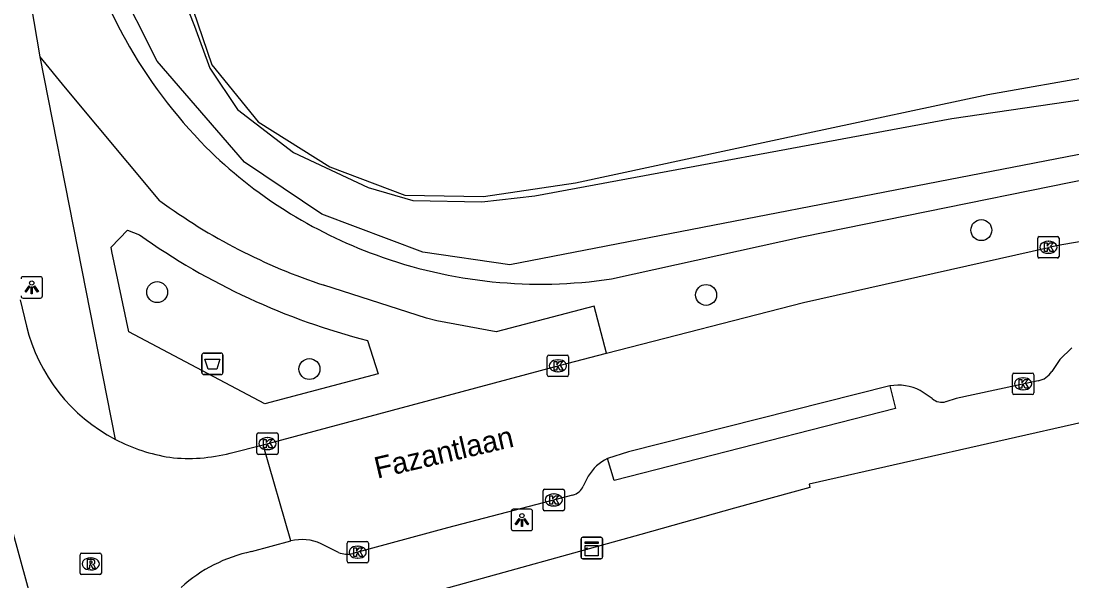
# Model space of a CAD drawing. Extents: x 161772 to 163123, y 383092 to 383917.
# Drawn here: x 161963.46 to 162012.54, y 383457.54 to 383483.68 of the extents above; entities that cross this region are included whole.
import ezdxf

# ---------------------------------------------------------------- set-up
doc = ezdxf.new("R2010")
doc.units = 0
for name, color, linetype in [('IMGEO_Afvalbak', 7, 'Continuous'), ('IMGEO_Boom', 7, 'Continuous'), ('IMGEO_Erf', 7, 'Continuous'), ('IMGEO_Groenvoorziening', 7, 'Continuous'), ('IMGEO_Kast', 7, 'Continuous'), ('IMGEO_Kolk', 7, 'Continuous'), ('IMGEO_Lichtpunt', 7, 'Continuous'), ('IMGEO_Openbare_ruimte_label', 7, 'Continuous'), ('IMGEO_Rijbaan_lokaal_gesloten', 7, 'Continuous'), ('IMGEO_Rijbaan_lokaal_open', 7, 'Continuous'), ('IMGEO_Rioolput', 7, 'Continuous'), ('IMGEO_Voetpad_gesloten', 7, 'Continuous'), ('IMGEO_Voetpad_open', 7, 'Continuous'), ('IMGEO_Waterloop', 7, 'Continuous')]:
    doc.layers.add(name, color=color, linetype=linetype)

msp = doc.modelspace()

# ---------------------------------------------------------------- linework, layer by layer
at = {"layer": 'IMGEO_Afvalbak'}
for p, q in [((161971.902, 383467.276), (161971.902, 383468.076)), ((161971.902, 383468.076), (161971.902, 383467.276)), ((161972.002, 383468.176), (161972.792, 383468.176)), ((161972.792, 383468.176), (161972.002, 383468.176)), ((161972.892, 383468.076), (161972.892, 383467.276)), ((161972.892, 383467.276), (161972.892, 383468.076)), ((161972.792, 383467.176), (161972.002, 383467.176)), ((161972.002, 383467.176), (161972.792, 383467.176))]:
    msp.add_line(p, q, dxfattribs=at)
msp.add_lwpolyline([(161972.045, 383467.89), (161972.749, 383467.89), (161972.6, 383467.42), (161972.194, 383467.42), (161972.045, 383467.89)], dxfattribs=at)
for centre, start, end in [((161972.002, 383468.076), 90, 180), ((161972.002, 383468.076), 90, 180), ((161972.792, 383468.076), 0, 90), ((161972.792, 383468.076), 360, 90), ((161972.002, 383467.276), 180, 270), ((161972.002, 383467.276), 180, 270), ((161972.792, 383467.276), 270, 0), ((161972.792, 383467.276), 270, 0)]:
    msp.add_arc(centre, 0.1, start, end, dxfattribs=at)
at = {"layer": 'IMGEO_Boom'}
for centre in [(162008.305, 383473.918), (161969.819, 383471.024), (161995.452, 383470.891), (161976.929, 383467.432)]:
    msp.add_circle(centre, 0.489, dxfattribs=at)
at = {"layer": 'IMGEO_Erf'}
msp.add_lwpolyline([(161968.172, 383505.868), (161969.003, 383500), (161971.06, 383485.483), (161972.364, 383481.627), (161974.528, 383478.971), (161977.883, 383476.873), (161981.383, 383475.556), (161985.059, 383475.485), (161989.359, 383476.124), (162000, 383478.407), (162008.602, 383480.252), (162023.973, 383482.964), (162024.66, 383484.243), (162056.089, 383487.148)], dxfattribs=at)
at = {"layer": 'IMGEO_Groenvoorziening'}
msp.add_lwpolyline([(161991.036, 383471.642), (162000, 383473.614), (162018.222, 383477.318), (162028.627, 383479.262), (162056.342, 383483.117)], dxfattribs=at)
for centre, radius, start, end in [((161988.729, 383494.13), 23.321, 198.7657, 209.0338), ((161988.635, 383494.083), 23.216, 209.0443, 224.575), ((161987.454, 383493.27), 21.806, 225.23, 250.1314), ((161987.728, 383493.685), 22.29, 249.8312, 278.534)]:
    msp.add_arc(centre, radius, start, end, dxfattribs=at)
at = {"layer": 'IMGEO_Kast'}
for p, q in [((161989.69, 383459.579), (161990.531, 383459.579)), ((161990.531, 383459.579), (161989.69, 383459.579)), ((161990.615, 383459.504), (161990.615, 383458.663)), ((161990.615, 383458.663), (161990.615, 383459.504)), ((161989.615, 383458.654), (161989.615, 383459.495)), ((161989.615, 383459.495), (161989.615, 383458.654)), ((161990.54, 383458.579), (161989.699, 383458.579)), ((161989.699, 383458.579), (161990.54, 383458.579))]:
    msp.add_line(p, q, dxfattribs=at)
for points in [[(161989.81, 383459.369), (161990.41, 383459.369), (161990.41, 383459.284), (161989.81, 383459.284), (161989.81, 383459.369)], [(161989.81, 383459.194), (161990.41, 383459.194), (161990.41, 383458.705), (161989.81, 383458.705), (161989.81, 383459.194)]]:
    msp.add_lwpolyline(points, dxfattribs=at)
msp.add_circle((161989.894, 383459.043), 0.0377, dxfattribs=at)
for centre, start, end in [((161989.693, 383459.501), 92.4484, 184.2845), ((161989.693, 383459.501), 92.4484, 184.2845), ((161990.537, 383459.501), 2.4484, 94.2845), ((161990.537, 383459.501), 2.4484, 94.2845), ((161989.693, 383458.657), 182.4484, 274.2845), ((161989.693, 383458.657), 182.4484, 274.2845), ((161990.537, 383458.657), 272.4484, 4.2845), ((161990.537, 383458.657), 272.4484, 4.2845)]:
    msp.add_arc(centre, 0.0779, start, end, dxfattribs=at)
at = {"layer": 'IMGEO_Kolk'}
for p, q in [((162010.937, 383472.691), (162010.937, 383473.543)), ((162011.012, 383473.617), (162011.864, 383473.617)), ((162011.425, 383473.397), (162011.45, 383473.397)), ((162011.938, 383473.543), (162011.938, 383472.691)), ((162011.448, 383472.837), (162011.423, 383472.837)), ((162011.864, 383472.617), (162011.012, 383472.617)), ((161988.031, 383467.158), (161988.031, 383468.01)), ((161988.106, 383468.084), (161988.958, 383468.084)), ((161988.519, 383467.864), (161988.544, 383467.864)), ((161989.032, 383468.01), (161989.032, 383467.158)), ((161988.958, 383467.084), (161988.106, 383467.084)), ((161988.542, 383467.304), (161988.517, 383467.304)), ((162009.755, 383466.317), (162009.755, 383467.169)), ((162009.83, 383467.243), (162010.682, 383467.243)), ((162010.243, 383467.023), (162010.268, 383467.023)), ((162010.756, 383467.169), (162010.756, 383466.317)), ((162010.266, 383466.463), (162010.241, 383466.463)), ((162010.682, 383466.243), (162009.83, 383466.243)), ((161974.543, 383464.45), (161975.395, 383464.45)), ((161974.468, 383463.524), (161974.468, 383464.376)), ((161974.956, 383464.23), (161974.981, 383464.23)), ((161975.469, 383464.376), (161975.469, 383463.524)), ((161975.395, 383463.45), (161974.543, 383463.45)), ((161974.979, 383463.67), (161974.954, 383463.67)), ((161987.838, 383460.895), (161987.838, 383461.747)), ((161987.913, 383461.821), (161988.765, 383461.821)), ((161988.326, 383461.601), (161988.351, 383461.601)), ((161988.839, 383461.747), (161988.839, 383460.895)), ((161988.349, 383461.041), (161988.324, 383461.041)), ((161988.765, 383460.821), (161987.913, 383460.821)), ((161978.684, 383458.456), (161978.684, 383459.308)), ((161978.759, 383459.382), (161979.611, 383459.382)), ((161979.172, 383459.162), (161979.197, 383459.162)), ((161979.685, 383459.308), (161979.685, 383458.456)), ((161979.195, 383458.602), (161979.17, 383458.602)), ((161979.611, 383458.382), (161978.759, 383458.382))]:
    msp.add_line(p, q, dxfattribs=at)
for points in [[(162010.937, 383472.691), (162010.937, 383473.543)], [(162011.012, 383473.617), (162011.864, 383473.617)], [(162011.258, 383473.317), (162011.381, 383473.317), (162011.381, 383473.166), (162011.511, 383473.317), (162011.675, 383473.317), (162011.529, 383473.166), (162011.682, 383472.917), (162011.53, 383472.917), (162011.445, 383473.081), (162011.381, 383473.014), (162011.381, 383472.917), (162011.258, 383472.917), (162011.258, 383473.317)], [(162011.938, 383473.543), (162011.938, 383472.691)], [(162011.864, 383472.617), (162011.012, 383472.617)], [(161988.031, 383467.158), (161988.031, 383468.01)], [(161988.106, 383468.084), (161988.958, 383468.084)], [(161989.032, 383468.01), (161989.032, 383467.158)], [(161988.352, 383467.784), (161988.475, 383467.784), (161988.475, 383467.633), (161988.605, 383467.784), (161988.769, 383467.784), (161988.623, 383467.633), (161988.776, 383467.384), (161988.624, 383467.384), (161988.539, 383467.548), (161988.475, 383467.481), (161988.475, 383467.384), (161988.352, 383467.384), (161988.352, 383467.784)], [(161988.958, 383467.084), (161988.106, 383467.084)], [(162009.755, 383466.317), (162009.755, 383467.169)], [(162009.83, 383467.243), (162010.682, 383467.243)], [(162010.076, 383466.943), (162010.199, 383466.943), (162010.199, 383466.792), (162010.329, 383466.943), (162010.493, 383466.943), (162010.347, 383466.792), (162010.5, 383466.543), (162010.348, 383466.543), (162010.263, 383466.707), (162010.199, 383466.64), (162010.199, 383466.543), (162010.076, 383466.543), (162010.076, 383466.943)], [(162010.756, 383467.169), (162010.756, 383466.317)], [(162010.682, 383466.243), (162009.83, 383466.243)], [(161974.543, 383464.45), (161975.395, 383464.45)], [(161974.468, 383463.524), (161974.468, 383464.376)], [(161974.789, 383464.15), (161974.912, 383464.15), (161974.912, 383463.999), (161975.042, 383464.15), (161975.206, 383464.15), (161975.06, 383463.999), (161975.213, 383463.75), (161975.061, 383463.75), (161974.976, 383463.914), (161974.912, 383463.847), (161974.912, 383463.75), (161974.789, 383463.75), (161974.789, 383464.15)], [(161975.469, 383464.376), (161975.469, 383463.524)], [(161975.395, 383463.45), (161974.543, 383463.45)], [(161987.838, 383460.895), (161987.838, 383461.747)], [(161987.913, 383461.821), (161988.765, 383461.821)], [(161988.159, 383461.521), (161988.282, 383461.521), (161988.282, 383461.37), (161988.412, 383461.521), (161988.576, 383461.521), (161988.43, 383461.37), (161988.583, 383461.121), (161988.431, 383461.121), (161988.346, 383461.285), (161988.282, 383461.218), (161988.282, 383461.121), (161988.159, 383461.121), (161988.159, 383461.521)], [(161988.839, 383461.747), (161988.839, 383460.895)], [(161988.765, 383460.821), (161987.913, 383460.821)], [(161978.684, 383458.456), (161978.684, 383459.308)], [(161978.759, 383459.382), (161979.611, 383459.382)], [(161979.005, 383459.082), (161979.128, 383459.082), (161979.128, 383458.931), (161979.258, 383459.082), (161979.422, 383459.082), (161979.276, 383458.931), (161979.429, 383458.682), (161979.277, 383458.682), (161979.192, 383458.846), (161979.128, 383458.779), (161979.128, 383458.682), (161979.005, 383458.682), (161979.005, 383459.082)], [(161979.685, 383459.308), (161979.685, 383458.456)], [(161979.611, 383458.382), (161978.759, 383458.382)]]:
    msp.add_lwpolyline(points, dxfattribs=at)
for centre, start, end in [((162011.014, 383473.541), 91.552, 178.448), ((162011.014, 383473.541), 91.552, 178.448), ((162011.862, 383473.541), 1.552, 88.448), ((162011.862, 383473.541), 1.552, 88.448), ((162011.014, 383472.693), 181.552, 268.448), ((162011.014, 383472.693), 181.552, 268.448), ((162011.862, 383472.693), 271.552, 358.448), ((162011.862, 383472.693), 271.552, 358.448), ((161988.108, 383468.008), 91.552, 178.448), ((161988.108, 383468.008), 91.552, 178.448), ((161988.956, 383468.008), 1.552, 88.448), ((161988.956, 383468.008), 1.552, 88.448), ((161988.108, 383467.16), 181.552, 268.448), ((161988.108, 383467.16), 181.552, 268.448), ((161988.956, 383467.16), 271.552, 358.448), ((161988.956, 383467.16), 271.552, 358.448), ((162009.832, 383467.167), 91.552, 178.448), ((162009.832, 383467.167), 91.552, 178.448), ((162010.68, 383467.167), 1.552, 88.448), ((162010.68, 383467.167), 1.552, 88.448), ((162009.832, 383466.319), 181.552, 268.448), ((162009.832, 383466.319), 181.552, 268.448), ((162010.68, 383466.319), 271.552, 358.448), ((162010.68, 383466.319), 271.552, 358.448), ((161974.545, 383464.374), 91.552, 178.448), ((161974.545, 383464.374), 91.552, 178.448), ((161975.393, 383464.374), 1.552, 88.448), ((161975.393, 383464.374), 1.552, 88.448), ((161974.545, 383463.526), 181.552, 268.448), ((161974.545, 383463.526), 181.552, 268.448), ((161975.393, 383463.526), 271.552, 358.448), ((161975.393, 383463.526), 271.552, 358.448), ((161987.915, 383461.745), 91.552, 178.448), ((161987.915, 383461.745), 91.552, 178.448), ((161988.763, 383461.745), 1.552, 88.448), ((161988.763, 383461.745), 1.552, 88.448), ((161987.915, 383460.897), 181.552, 268.448), ((161987.915, 383460.897), 181.552, 268.448), ((161988.763, 383460.897), 271.552, 358.448), ((161988.763, 383460.897), 271.552, 358.448), ((161978.761, 383459.306), 91.552, 178.448), ((161978.761, 383459.306), 91.552, 178.448), ((161979.609, 383459.306), 1.552, 88.448), ((161979.609, 383459.306), 1.552, 88.448), ((161978.761, 383458.458), 181.552, 268.448), ((161978.761, 383458.458), 181.552, 268.448), ((161979.609, 383458.458), 271.552, 358.448), ((161979.609, 383458.458), 271.552, 358.448)]:
    msp.add_arc(centre, 0.0765, start, end, dxfattribs=at)
for centre, major_axis, ratio, start_param, end_param in [((162011.424, 383473.117), (-0.387, 0.002), 0.722429, 4.712389, 7.853982), ((162011.449, 383473.117), (-0.39, 0.002), 0.717154, 1.570796, 4.712389), ((161988.518, 383467.584), (-0.387, 0.002), 0.722429, 4.712389, 7.853982), ((161988.543, 383467.584), (-0.39, 0.002), 0.717154, 1.570796, 4.712389), ((162010.242, 383466.743), (-0.387, 0.002), 0.722429, 4.712389, 7.853982), ((162010.267, 383466.743), (-0.39, 0.002), 0.717154, 1.570796, 4.712389), ((161974.955, 383463.95), (-0.387, 0.002), 0.722429, 4.712389, 7.853982), ((161974.98, 383463.95), (-0.39, 0.002), 0.717154, 1.570796, 4.712389), ((161988.325, 383461.321), (-0.387, 0.002), 0.722429, 4.712389, 7.853982), ((161988.35, 383461.321), (-0.39, 0.002), 0.717154, 1.570796, 4.712389), ((161979.171, 383458.882), (-0.387, 0.002), 0.722429, 4.712389, 7.853982), ((161979.196, 383458.882), (-0.39, 0.002), 0.717154, 1.570796, 4.712389)]:
    msp.add_ellipse(centre, major_axis=major_axis, ratio=ratio, start_param=start_param, end_param=end_param, dxfattribs=at)
at = {"layer": 'IMGEO_Lichtpunt'}
for p, q in [((161964.363, 383471.745), (161963.555, 383471.745)), ((161964.363, 383471.745), (161963.555, 383471.745)), ((161964.457, 383470.843), (161964.457, 383471.65)), ((161964.457, 383470.843), (161964.457, 383471.65)), ((161963.555, 383470.749), (161964.363, 383470.749)), ((161963.555, 383470.749), (161964.363, 383470.749)), ((161986.353, 383460.79), (161986.353, 383459.983)), ((161986.353, 383460.79), (161986.353, 383459.983)), ((161987.255, 383460.885), (161986.447, 383460.885)), ((161987.255, 383460.885), (161986.447, 383460.885)), ((161987.349, 383459.983), (161987.349, 383460.79)), ((161987.349, 383459.983), (161987.349, 383460.79)), ((161986.447, 383459.889), (161987.255, 383459.889)), ((161986.447, 383459.889), (161987.255, 383459.889))]:
    msp.add_line(p, q, dxfattribs=at)
for points in [[(161963.835, 383471.314), (161963.874, 383471.286), (161963.686, 383471.024), (161963.648, 383471.051), (161963.835, 383471.314)], [(161964.047, 383471.286), (161964.085, 383471.313), (161964.272, 383471.051), (161964.233, 383471.023), (161964.047, 383471.286)], [(161963.937, 383471.266), (161963.984, 383471.266), (161963.984, 383470.944), (161963.937, 383470.944), (161963.937, 383471.266)], [(161986.727, 383460.454), (161986.766, 383460.426), (161986.578, 383460.164), (161986.54, 383460.191), (161986.727, 383460.454)], [(161986.829, 383460.406), (161986.876, 383460.406), (161986.876, 383460.084), (161986.829, 383460.084), (161986.829, 383460.406)], [(161986.939, 383460.426), (161986.977, 383460.453), (161987.164, 383460.191), (161987.125, 383460.163), (161986.939, 383460.426)]]:
    msp.add_lwpolyline(points, dxfattribs=at)
for centre in [(161963.96, 383471.448), (161986.852, 383460.588)]:
    msp.add_circle(centre, 0.0994, dxfattribs=at)
for centre, start, end in [((161963.555, 383471.65), 90, 180), ((161963.555, 383471.65), 90, 180), ((161964.363, 383471.65), 0, 90), ((161964.363, 383471.65), 0, 90), ((161963.555, 383470.843), 180, 270), ((161963.555, 383470.843), 180, 270), ((161964.363, 383470.843), 270, 0), ((161964.363, 383470.843), 270, 360), ((161986.447, 383460.79), 90, 180), ((161986.447, 383460.79), 90, 180), ((161987.255, 383460.79), 0, 90), ((161987.255, 383460.79), 0, 90), ((161986.447, 383459.983), 180, 270), ((161986.447, 383459.983), 180, 270), ((161987.255, 383459.983), 270, 0), ((161987.255, 383459.983), 270, 360)]:
    msp.add_arc(centre, 0.0946, start, end, dxfattribs=at)
at = {"layer": 'IMGEO_Rijbaan_lokaal_gesloten'}
for points in [[(161990.801, 383468.172), (162000, 383470.537), (162011.434, 383473.114)], [(162012.538, 383468.424), (162011.976, 383467.874), (162011.596, 383467.32)], [(161974.762, 383463.893), (161988.586, 383467.602), (161990.801, 383468.172)], [(162010.958, 383466.884), (162007.128, 383466.05), (162006.649, 383465.909)], [(162004.039, 383466.644), (161991.825, 383463.563), (161990.842, 383463.254)], [(162006.015, 383466.052), (162005.454, 383466.429)], [(161989.949, 383462.434), (161989.716, 383461.969)], [(161989.219, 383461.551), (161983.369, 383460.024), (161978.957, 383458.822)], [(161978.292, 383458.873), (161977.473, 383459.274)]]:
    msp.add_lwpolyline(points, dxfattribs=at)
for centre, radius, start, end in [((162075.46, 383119.465), 359.398, 96.99366, 100.26192), ((162010.791, 383467.813), 0.944, 280.1965, 328.4998), ((162004.428, 383464.439), 2.239, 62.7237, 99.997), ((162006.464, 383466.565), 0.681, 228.8036, 285.7755), ((161991.776, 383461.341), 2.129, 116.0176, 149.102), ((161989.084, 383462.217), 0.679, 281.5037, 338.6271), ((161976.587, 383457.409), 2.065, 64.5739, 104.7446), ((161978.695, 383459.763), 0.977, 245.6572, 285.5718)]:
    msp.add_arc(centre, radius, start, end, dxfattribs=at)
at = {"layer": 'IMGEO_Rijbaan_lokaal_open'}
for points in [[(161963.422, 383470.668), (161963.711, 383469.44)], [(161973.234, 383463.506), (161974.762, 383463.893)], [(161976.061, 383459.406), (161974.762, 383463.893)], [(161964.092, 383456.148), (161963.068, 383459.895)], [(161974.222, 383458.912), (161976.061, 383459.406)]]:
    msp.add_lwpolyline(points, dxfattribs=at)
for centre, radius, start, end in [((161971.658, 383471.403), 8.186, 193.8732, 242.4498), ((161971.655, 383471.388), 8.171, 242.4223, 261.2368), ((161971.3, 383471.012), 7.751, 263.4089, 284.4508), ((161975.725, 383451.89), 7.181, 102.0802, 131.8284)]:
    msp.add_arc(centre, radius, start, end, dxfattribs=at)
at = {"layer": 'IMGEO_Rioolput'}
for p, q in [((161966.216, 383457.911), (161966.216, 383458.763)), ((161966.291, 383458.837), (161967.143, 383458.837)), ((161966.704, 383458.617), (161966.729, 383458.617)), ((161967.217, 383458.763), (161967.217, 383457.911)), ((161966.727, 383458.057), (161966.702, 383458.057)), ((161967.143, 383457.837), (161966.291, 383457.837))]:
    msp.add_line(p, q, dxfattribs=at)
for points in [[(161966.216, 383457.911), (161966.216, 383458.763)], [(161966.291, 383458.837), (161967.143, 383458.837)], [(161966.805, 383458.535), (161966.553, 383458.537), (161966.553, 383458.137)], [(161967.217, 383458.763), (161967.217, 383457.911)], [(161966.553, 383458.137), (161966.677, 383458.137), (161966.677, 383458.299), (161966.688, 383458.299)], [(161966.731, 383458.456), (161966.677, 383458.456), (161966.677, 383458.375)], [(161966.677, 383458.375), (161966.729, 383458.375)], [(161966.735, 383458.27), (161966.806, 383458.137), (161966.946, 383458.137), (161966.881, 383458.263)], [(161967.143, 383457.837), (161966.291, 383457.837)]]:
    msp.add_lwpolyline(points, dxfattribs=at)
for centre, radius, start, end in [((161966.293, 383458.761), 0.0765, 91.552, 178.448), ((161966.293, 383458.761), 0.0765, 91.552, 178.448), ((161966.804, 383458.425), 0.109, 350.3612, 89.416), ((161967.141, 383458.761), 0.0765, 1.552, 88.448), ((161967.141, 383458.761), 0.0765, 1.552, 88.448), ((161966.687, 383458.246), 0.0533, 26.0293, 88.6989), ((161966.713, 383458.564), 0.19, 274.7715, 282.9687), ((161966.737, 383458.36), 0.0964, 77.0061, 93.1865), ((161966.751, 383458.417), 0.0378, 276.6634, 79.6772), ((161966.802, 383458.425), 0.112, 277.5842, 350.9817), ((161966.786, 383458.21), 0.108, 29.5134, 73.7905), ((161966.293, 383457.913), 0.0765, 181.552, 268.448), ((161966.293, 383457.913), 0.0765, 181.552, 268.448), ((161967.141, 383457.913), 0.0765, 271.552, 358.448), ((161967.141, 383457.913), 0.0765, 271.552, 358.448)]:
    msp.add_arc(centre, radius, start, end, dxfattribs=at)
for centre, major_axis, ratio, start_param, end_param in [((161966.703, 383458.337), (-0.387, 0.002), 0.722429, 4.712389, 7.853982), ((161966.728, 383458.337), (-0.39, 0.002), 0.717154, 1.570796, 4.712389)]:
    msp.add_ellipse(centre, major_axis=major_axis, ratio=ratio, start_param=start_param, end_param=end_param, dxfattribs=at)
at = {"layer": 'IMGEO_Voetpad_gesloten'}
for points in [[(161967.872, 383464.145), (161964.359, 383482.012)], [(161969.946, 383475.291), (161965.544, 383480.553), (161964.359, 383482.012)], [(161968.498, 383469.168), (161967.702, 383472.922), (161967.668, 383473.125), (161968.427, 383473.912), (161968.995, 383473.693)], [(161990.801, 383468.172), (161990.219, 383470.372), (161985.654, 383469.166), (161982.884, 383469.691), (161982.392, 383469.803), (161977.609, 383471.347)], [(161979.648, 383468.766), (161980.142, 383467.215), (161974.847, 383465.816), (161968.498, 383469.168)]]:
    msp.add_lwpolyline(points, dxfattribs=at)
for centre, radius, start, end in [((161986.112, 383497.284), 27.295, 233.6823, 251.8496), ((161987.624, 383499.992), 32.229, 234.688, 255.6711)]:
    msp.add_arc(centre, radius, start, end, dxfattribs=at)
at = {"layer": 'IMGEO_Voetpad_open'}
for points in [[(161964.359, 383482.012), (161963.495, 383487.065)], [(162004.039, 383466.644), (162004.29, 383465.591), (161991.155, 383462.23), (161990.842, 383463.254)], [(162013.474, 383465.049), (162000.265, 383462.051), (162000.295, 383461.907), (161996.785, 383460.931), (161992.404, 383459.714), (161973.318, 383454.411), (161972.09, 383452.564)]]:
    msp.add_lwpolyline(points, dxfattribs=at)
at = {"layer": 'IMGEO_Waterloop'}
for points in [[(161970.806, 383485.391), (161971.56, 383483.438), (161972.271, 383481.474), (161973.577, 383479.552), (161976.188, 383477.535), (161979.67, 383475.901), (161981.751, 383475.306), (161984.978, 383475.242), (161987.462, 383475.518), (162006.931, 383479.128), (162055.594, 383486.262)], [(162055.848, 383483.969), (162012.791, 383477.429), (161986.294, 383472.291), (161982.218, 383472.886), (161977.504, 383474.669), (161973.895, 383477.09), (161969.819, 383481.803), (161967.908, 383485.625)]]:
    msp.add_lwpolyline(points, dxfattribs=at)

# ---------------------------------------------------------------- texts
at = {"layer": 'IMGEO_Openbare_ruimte_label'}
msp.add_text('Fazantlaan', height=1, rotation=13.1749, dxfattribs=at).set_placement((161980.094, 383462.312))

doc.saveas('drawing.dxf')
